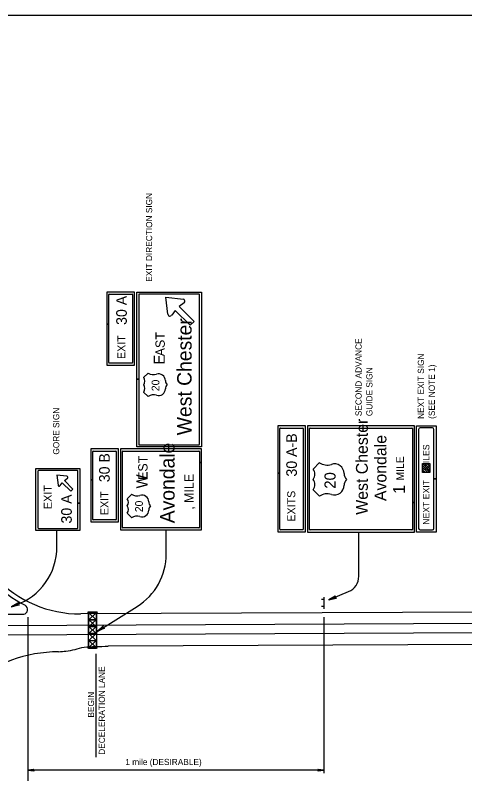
# Model space of a CAD drawing. Extents: x 644898 to 648326, y 298294 to 300670.
# Drawn here: x 646164.6 to 646382.5, y 299694 to 300061.5 of the extents above; entities that cross this region are included whole.
import ezdxf

# ---------------------------------------------------------------- set-up
doc = ezdxf.new("R2010")
doc.units = 0
doc.layers.add('1', color=7, linetype='Continuous')
doc.layers.add('2', color=7, linetype='Continuous')

msp = doc.modelspace()

# ---------------------------------------------------------------- linework, layer by layer
at = {"layer": '1'}
msp.add_line((645779.32, 300061.49), (646565.32, 300061.49), dxfattribs=at)
at = {"layer": '2'}
for p, q in [((646222.45, 299927.38), (646208.95, 299927.38)), ((646208.95, 299927.38), (646208.95, 299911.84)), ((646209.95, 299911.84), (646209.95, 299926.13)), ((646210.2, 299926.38), (646221.2, 299926.38)), ((646221.45, 299926.13), (646221.45, 299893.26)), ((646222.45, 299892.01), (646222.45, 299927.38)), ((646223.45, 299885.2), (646223.45, 299927.38)), ((646223.45, 299927.38), (646254.82, 299927.38)), ((646253.57, 299926.38), (646224.45, 299926.38)), ((646224.45, 299926.38), (646224.45, 299885.2)), ((646253.82, 299853.63), (646253.82, 299926.13)), ((646254.82, 299927.38), (646254.82, 299852.38)), ((646238.57, 299916.63), (646237.57, 299924.88)), ((646237.57, 299924.88), (646246.07, 299923.88)), ((646246.45, 299922.13), (646244.07, 299920.38)), ((646244.07, 299920.38), (646251.32, 299913.13)), ((646242.07, 299918.51), (646240.45, 299916.13)), ((646249.32, 299911.26), (646242.07, 299918.51)), ((646209.95, 299911.84), (646208.95, 299911.84)), ((646208.95, 299911.84), (646208.95, 299892.01)), ((646208.95, 299911.84), (646209.95, 299911.84)), ((646209.95, 299893.26), (646209.95, 299911.84)), ((646251.32, 299913.13), (646249.32, 299911.26)), ((646221.2, 299893.01), (646210.2, 299893.01)), ((646208.95, 299892.01), (646222.45, 299892.01)), ((646226.82, 299886.01), (646229.07, 299888.13)), ((646234.2, 299887.76), (646234.2, 299887.76)), ((646224.45, 299885.2), (646223.45, 299885.2)), ((646223.45, 299852.38), (646223.45, 299885.2)), ((646223.45, 299885.2), (646224.45, 299885.2)), ((646224.45, 299885.2), (646224.45, 299853.63)), ((646232.57, 299882.51), (646232.57, 299882.51)), ((646232.57, 299882.51), (646232.57, 299882.51)), ((646232.57, 299882.51), (646232.57, 299882.51)), ((646232.57, 299882.51), (646232.57, 299882.51)), ((646232.57, 299882.51), (646232.57, 299882.51)), ((646232.57, 299882.51), (646232.57, 299882.51)), ((646234.82, 299884.76), (646234.82, 299884.76)), ((646237.32, 299884.38), (646237.32, 299884.38)), ((646229.07, 299876.76), (646226.82, 299878.88)), ((646237.32, 299880.51), (646237.32, 299880.51)), ((646305.2, 299862.51), (646291.82, 299862.51)), ((646291.82, 299862.51), (646291.82, 299839.59)), ((646292.82, 299839.59), (646292.82, 299861.26)), ((646293.07, 299861.51), (646303.95, 299861.51)), ((646304.2, 299861.26), (646304.2, 299812.48)), ((646305.2, 299811.23), (646305.2, 299862.51)), ((646358.07, 299862.51), (646306.2, 299862.51)), ((646306.2, 299862.51), (646306.2, 299811.13)), ((646307.2, 299812.38), (646307.2, 299861.26)), ((646307.45, 299861.51), (646356.82, 299861.51)), ((646357.07, 299861.26), (646357.07, 299825.39)), ((646358.07, 299825.39), (646358.07, 299862.51)), ((646359.07, 299811.13), (646359.07, 299862.63)), ((646359.07, 299862.63), (646368.51, 299862.63)), ((646360.07, 299860.88), (646360.07, 299812.88)), ((646366.76, 299861.63), (646360.82, 299861.63)), ((646367.51, 299836.84), (646367.51, 299860.88)), ((646368.51, 299862.63), (646368.51, 299836.84)), ((646224.7, 299853.38), (646253.57, 299853.38)), ((646214.57, 299851.38), (646201.2, 299851.38)), ((646201.2, 299851.38), (646201.2, 299836.46)), ((646202.2, 299836.46), (646202.2, 299850.13)), ((646202.45, 299850.38), (646213.32, 299850.38)), ((646213.57, 299850.13), (646213.57, 299817.26)), ((646214.57, 299816.01), (646214.57, 299851.38)), ((646254.82, 299851.38), (646215.57, 299851.38)), ((646215.57, 299851.38), (646215.57, 299812.13)), ((646216.57, 299813.38), (646216.57, 299850.13)), ((646216.82, 299850.38), (646253.57, 299850.38)), ((646254.82, 299852.38), (646223.45, 299852.38)), ((646253.82, 299850.13), (646253.82, 299844.87)), ((646254.82, 299844.87), (646254.82, 299851.38)), ((646174.57, 299811.88), (646174.57, 299841.88)), ((646174.57, 299841.88), (646195.95, 299841.88)), ((646195.95, 299841.88), (646195.95, 299825.1)), ((646253.82, 299844.87), (646254.82, 299844.87)), ((646254.82, 299844.87), (646253.82, 299844.87)), ((646253.82, 299844.87), (646253.82, 299813.38)), ((646254.82, 299812.13), (646254.82, 299844.87)), ((646308.95, 299841.63), (646312.07, 299844.76)), ((646319.2, 299844.13), (646319.2, 299844.13)), ((646365.57, 299840.82), (646362.02, 299844.37)), ((646365.42, 299839.91), (646362.02, 299843.31)), ((646364.45, 299839.91), (646362.02, 299842.34)), ((646365.57, 299841.79), (646362.97, 299844.39)), ((646365.57, 299842.8), (646363.98, 299844.39)), ((646365.57, 299843.78), (646364.96, 299844.39)), ((646175.57, 299840.63), (646175.57, 299813.13)), ((646194.7, 299840.88), (646175.82, 299840.88)), ((646189.6, 299838.15), (646184.8, 299838.69)), ((646184.8, 299838.69), (646185.34, 299833.89)), ((646194.95, 299825.1), (646194.95, 299840.63)), ((646292.82, 299839.59), (646291.82, 299839.59)), ((646291.82, 299839.59), (646291.82, 299811.23)), ((646291.82, 299839.59), (646292.82, 299839.59)), ((646292.82, 299812.48), (646292.82, 299839.59)), ((646323.95, 299839.51), (646323.95, 299839.51)), ((646363.44, 299839.91), (646362.02, 299841.32)), ((646362.51, 299839.91), (646362.02, 299840.39)), ((646186.34, 299833.62), (646187.39, 299835.04)), ((646187.39, 299835.04), (646191.52, 299830.91)), ((646188.45, 299836.1), (646189.87, 299837.15)), ((646192.58, 299831.97), (646188.45, 299836.1)), ((646202.2, 299836.46), (646201.2, 299836.46)), ((646201.2, 299836.46), (646201.2, 299816.01)), ((646201.2, 299836.46), (646202.2, 299836.46)), ((646202.2, 299817.26), (646202.2, 299836.46)), ((646317.2, 299836.63), (646317.2, 299836.63)), ((646317.2, 299836.63), (646317.2, 299836.63)), ((646368.51, 299836.84), (646367.51, 299836.84)), ((646367.51, 299812.88), (646367.51, 299836.84)), ((646367.51, 299836.84), (646368.51, 299836.84)), ((646368.51, 299836.84), (646368.51, 299811.13)), ((646191.52, 299830.91), (646192.58, 299831.97)), ((646312.07, 299828.51), (646308.95, 299831.63)), ((646323.95, 299833.76), (646323.95, 299833.76)), ((646218.82, 299827.26), (646221.07, 299829.51)), ((646226.07, 299829.01), (646226.07, 299829.01)), ((646194.95, 299825.1), (646195.95, 299825.1)), ((646195.95, 299825.1), (646194.95, 299825.1)), ((646194.95, 299813.13), (646194.95, 299825.1)), ((646195.95, 299825.1), (646195.95, 299811.88)), ((646224.57, 299823.76), (646224.57, 299823.76)), ((646224.57, 299823.76), (646224.57, 299823.76)), ((646224.57, 299823.76), (646224.57, 299823.76)), ((646224.57, 299823.76), (646224.57, 299823.76)), ((646229.32, 299825.76), (646229.32, 299825.76)), ((646358.07, 299825.39), (646357.07, 299825.39)), ((646357.07, 299825.39), (646357.07, 299812.38)), ((646357.07, 299825.39), (646358.07, 299825.39)), ((646358.07, 299811.13), (646358.07, 299825.39)), ((646221.07, 299818.01), (646218.82, 299820.26)), ((646229.32, 299821.76), (646229.32, 299821.76)), ((646201.2, 299816.01), (646214.57, 299816.01)), ((646213.32, 299817.01), (646202.45, 299817.01)), ((646175.82, 299812.88), (646194.7, 299812.88)), ((646215.57, 299812.13), (646254.82, 299812.13)), ((646253.57, 299813.13), (646216.82, 299813.13)), ((646237.82, 299800.53), (646237.82, 299812.13)), ((646303.95, 299812.23), (646293.07, 299812.23)), ((646356.82, 299812.13), (646307.45, 299812.13)), ((646360.82, 299812.13), (646366.76, 299812.13)), ((646195.95, 299811.88), (646174.57, 299811.88)), ((646184.82, 299804.04), (646184.82, 299811.88)), ((646291.82, 299811.23), (646305.2, 299811.23)), ((646306.2, 299811.13), (646358.07, 299811.13)), ((646331.07, 299789.63), (646331.07, 299811.13)), ((646368.51, 299811.13), (646359.07, 299811.13)), ((646314.2, 299779.51), (646314.2, 299773.88)), ((646316.57, 299778.26), (646326.07, 299782.26)), ((646314.2, 299778.38), (646313.07, 299778.38)), ((646565.32, 299773.14), (646196.32, 299771.51)), ((646200.32, 299772.01), (646203.82, 299768.63)), ((646203.82, 299772.01), (646200.32, 299768.63)), ((646204.32, 299763.01), (646223.68, 299775.06)), ((646314.2, 299775.01), (646313.07, 299775.01)), ((646168.7, 299771.26), (646108.07, 299771.13)), ((646170.7, 299769.88), (646170.7, 299694.26)), ((646200.32, 299768.63), (646203.82, 299765.38)), ((646203.82, 299768.63), (646200.32, 299765.38)), ((646314.2, 299769.88), (646314.2, 299694.26)), ((646565.32, 299767.51), (646047.95, 299765.26)), ((646200.32, 299765.38), (646203.82, 299762.01)), ((646203.82, 299765.38), (646200.32, 299762.01)), ((646565.32, 299763.14), (646047.2, 299760.76)), ((646200.32, 299762.01), (646203.82, 299758.63)), ((646203.82, 299762.01), (646200.32, 299758.63)), ((646202.07, 299763.63), (646202.07, 299763.63)), ((646200.32, 299758.63), (646203.82, 299755.26)), ((646203.82, 299758.63), (646200.32, 299755.26)), ((646565.32, 299757.51), (646209.7, 299755.88)), ((646203.82, 299755.26), (646203.82, 299755.26)), ((646203.7, 299752.13), (646203.7, 299702.01)), ((646170.7, 299742.38), (646170.7, 299667.38)), ((646314.2, 299695.76), (646170.7, 299695.76))]:
    msp.add_line(p, q, dxfattribs=at)
for points in [[(646365.57, 299839.91), (646362.02, 299839.91), (646362.02, 299844.39), (646365.57, 299844.39)], [(646200.32, 299768.63), (646200.32, 299772.01), (646203.82, 299772.01), (646203.82, 299768.63)], [(646200.32, 299765.38), (646200.32, 299768.63), (646203.82, 299768.63), (646203.82, 299765.38)], [(646200.32, 299762.01), (646200.32, 299765.38), (646203.82, 299765.38), (646203.82, 299762.01)], [(646200.32, 299755.26), (646200.32, 299758.63), (646203.82, 299758.63), (646203.82, 299755.26)]]:
    msp.add_lwpolyline(points, close=True, dxfattribs=at)
for points in [[(646319.95, 299779.13), (646319.82, 299779.38), (646316.57, 299778.26), (646319.95, 299779.13), (646320.32, 299779.13), (646316.57, 299778.26), (646319.57, 299779.76), (646319.7, 299780.01), (646316.57, 299778.26), (646319.82, 299780.26), (646319.7, 299780.01)], [(646166.11, 299775.84), (646166.09, 299776.09), (646162.79, 299774.98), (646166.11, 299775.84), (646166.49, 299775.74), (646162.79, 299774.98), (646165.69, 299776.44), (646165.93, 299776.71), (646162.79, 299774.98), (646166.16, 299776.97), (646165.93, 299776.71)], [(646199.95, 299772.01), (646199.95, 299754.88)], [(646203.82, 299772.38), (646200.32, 299772.38)], [(646204.2, 299754.88), (646204.2, 299772.01)], [(646207.45, 299764.51), (646207.32, 299764.76), (646204.32, 299763.01), (646207.45, 299764.51), (646207.82, 299764.51), (646204.32, 299763.01), (646206.95, 299765.01), (646207.07, 299765.26), (646204.32, 299763.01), (646207.2, 299765.63), (646207.07, 299765.26)], [(646200.32, 299754.88), (646203.82, 299754.88)], [(646173.55, 299695.4), (646173.45, 299695.61), (646170.7, 299695.76), (646173.55, 299695.4), (646173.7, 299695.28), (646170.7, 299695.76), (646173.44, 299695.89), (646173.54, 299696.1), (646170.7, 299695.76), (646173.7, 299696.24), (646173.54, 299696.1)], [(646311.34, 299696.12), (646311.45, 299695.91), (646314.2, 299695.76), (646311.34, 299696.12), (646311.2, 299696.24), (646314.2, 299695.76), (646311.45, 299695.62), (646311.35, 299695.42), (646314.2, 299695.76), (646311.2, 299695.28), (646311.35, 299695.42)]]:
    msp.add_lwpolyline(points, dxfattribs=at)
for centre in [(646200.18, 299772.25), (646203.97, 299772.25), (646200.18, 299755.03), (646203.97, 299755.03)]:
    msp.add_circle(centre, 0.301, dxfattribs=at)
for centre, radius, start, end in [((646210.2, 299926.13), 0.25, 90, 180), ((646221.2, 299926.13), 0.25, 0, 90), ((646224.7, 299926.13), 0.25, 90, 180), ((646253.57, 299926.13), 0.25, 0, 90), ((646245.89, 299922.93), 0.978, 303.2449, 87.1516), ((646239.59, 299916.7), 0.978, 184.8565, 325.522), ((646210.2, 299893.26), 0.25, 180, 270), ((646221.2, 299893.26), 0.25, 270, 360), ((646224.54, 299884.24), 2.93, 323.136, 36.864), ((646231.64, 299891.9), 4.55, 235.4253, 288.1711), ((646234.1, 299884.49), 3.26, 0.0047, 108.548), ((646224.54, 299880.72), 2.93, 323.136, 36.864), ((646240.12, 299884.49), 2.76, 180, 226.2725), ((646240.12, 299880.47), 2.76, 133.7275, 180), ((646234.1, 299880.47), 3.26, 251.452, 359.9953), ((646231.64, 299873.06), 4.55, 71.8289, 124.5747), ((646293.07, 299861.26), 0.25, 90, 180), ((646303.95, 299861.26), 0.25, 0, 90), ((646307.45, 299861.26), 0.25, 90, 180), ((646356.82, 299861.26), 0.25, 0, 90), ((646360.82, 299860.88), 0.75, 90, 180), ((646366.76, 299860.88), 0.75, 0, 90), ((646224.7, 299853.63), 0.25, 180, 270), ((646253.57, 299853.63), 0.25, 270, 360), ((646202.45, 299850.13), 0.25, 90, 180), ((646213.32, 299850.13), 0.25, 0, 90), ((646216.82, 299850.13), 0.25, 90, 180), ((646253.57, 299850.13), 0.25, 0, 90), ((646305.62, 299839.13), 4.18, 323.136, 36.864), ((646315.75, 299850.08), 6.5, 235.4253, 288.1711), ((646319.26, 299839.49), 4.66, 0.0047, 108.548), ((646175.82, 299840.63), 0.25, 90, 180), ((646189.53, 299837.6), 0.559, 306.5527, 83.5801), ((646194.7, 299840.63), 0.25, 0, 90), ((646327.86, 299839.49), 3.94, 180, 226.2725), ((646305.62, 299834.12), 4.18, 323.136, 36.864), ((646327.86, 299833.76), 3.94, 133.7275, 180), ((646185.89, 299833.95), 0.559, 186.4218, 323.4493), ((646319.26, 299833.76), 4.66, 251.452, 359.9953), ((646216.49, 299825.52), 2.93, 323.136, 36.864), ((646223.59, 299833.19), 4.55, 235.4253, 288.1711), ((646226.04, 299825.77), 3.26, 0.0047, 108.548), ((646315.75, 299823.16), 6.5, 71.8289, 124.5747), ((646216.49, 299822.01), 2.93, 323.136, 36.864), ((646232.06, 299825.77), 2.76, 180, 226.2725), ((646232.06, 299821.76), 2.76, 133.7275, 180), ((646226.04, 299821.76), 3.26, 251.452, 359.9953), ((646202.45, 299817.26), 0.25, 180, 270), ((646213.32, 299817.26), 0.25, 270, 360), ((646223.59, 299814.34), 4.55, 71.8289, 124.5747), ((646175.82, 299813.13), 0.25, 180, 270), ((646194.7, 299813.13), 0.25, 270, 0), ((646216.82, 299813.38), 0.25, 180, 270), ((646253.57, 299813.38), 0.25, 270, 360), ((646293.07, 299812.48), 0.25, 180, 270), ((646303.95, 299812.48), 0.25, 270, 360), ((646307.45, 299812.38), 0.25, 180, 270), ((646356.82, 299812.38), 0.25, 270, 360), ((646360.82, 299812.88), 0.75, 180, 270), ((646366.76, 299812.88), 0.75, 270, 0), ((646154.82, 299804.04), 30, 289.3407, 0), ((646207.82, 299800.53), 30, 301.9022, 0), ((646196.02, 299827.44), 58.23, 223.3194, 242.7882), ((646196.02, 299827.44), 55.99, 223.3194, 270.2525), ((646323.07, 299789.68), 8, 292.4631, 0), ((646168.35, 299773.61), 2.3, 278.0002, 63.1291), ((646185.95, 299685.96), 67.18, 90.2526, 130)]:
    msp.add_arc(centre, radius, start, end, dxfattribs=at)
msp.add_spline([(646185.7, 299753.13), (646189.2, 299753.51), (646193.57, 299754.26), (646198.07, 299755.38), (646203.32, 299755.63), (646209.7, 299755.88)], degree=3, dxfattribs=at)

# ---------------------------------------------------------------- texts
for s, height, rotation, p in [('EXIT DIRECTION SIGN', 3, 90, (646230.95, 299932.38)), ('30 A', 5.125, 90, (646218.67, 299911.46)), ('West Chester', 6.9997, 89.9998, (646250.07, 299858.01)), ('AST', 4.5, 90, (646237.07, 299896.26)), ('EXIT', 3.875, 90, (646217.94, 299894.93)), ('SECOND ADVANCE', 3, 90, (646332.45, 299867.26)), ('E', 5.38, 90, (646237.07, 299892.26)), ('NEXT EXIT SIGN', 3, 90, (646362.67, 299865.96)), ('GUIDE SIGN', 3, 90, (646337.7, 299867.26)), ('(SEE NOTE 1)', 3, 90, (646367.92, 299865.96)), ('20', 3.75, 90, (646234.45, 299879.38)), ('GORE SIGN', 3, 90, (646185.95, 299848.63)), ('West Chester', 5.7435, 90, (646335.45, 299819.51)), ('30 A-B', 5.125, 90, (646301.07, 299837.99)), ('Avondale', 5.743, 90, (646344.45, 299826.13)), ('Avondale', 7, 90, (646241.82, 299815.38)), ('NEXT EXIT    MILES', 3.1342, 90, (646365.28, 299814.68)), ('30 B', 5.125, 90, (646210.39, 299835.25)), ('EST', 4.5, 90, (646228.7, 299836.38)), ('MILE', 3.749, 90, (646352.95, 299836.13)), ('MILE', 3.749, 90, (646352.95, 299836.13)), ('W', 5.38, 90, (646228.7, 299832.26)), ('‚ MILE', 4.546, 90, (646251.07, 299822.13)), ('20', 5.375, 90, (646319.82, 299832.13)), ('EXIT', 3.917, 90, (646182.32, 299822.26)), ('EXIT', 3.875, 90, (646209.78, 299819.33)), ('EXITS', 3.875, 90, (646300.29, 299816.16)), ('1', 5.74, 90, (646353.45, 299829.63)), ('30 A', 5.125, 90, (646192.01, 299815.25)), ('20', 3.75, 90, (646226.45, 299820.76)), ('DECELERATION LANE', 3, 90, (646208.07, 299703.26)), ('BEGIN', 3, 90, (646202.82, 299721.26))]:
    msp.add_text(s, height=height, rotation=rotation, dxfattribs=at).set_placement(p)
msp.add_text('1 mile (DESIRABLE)', height=3, dxfattribs=at).set_placement((646217.96, 299698.26))

doc.saveas('drawing.dxf')
